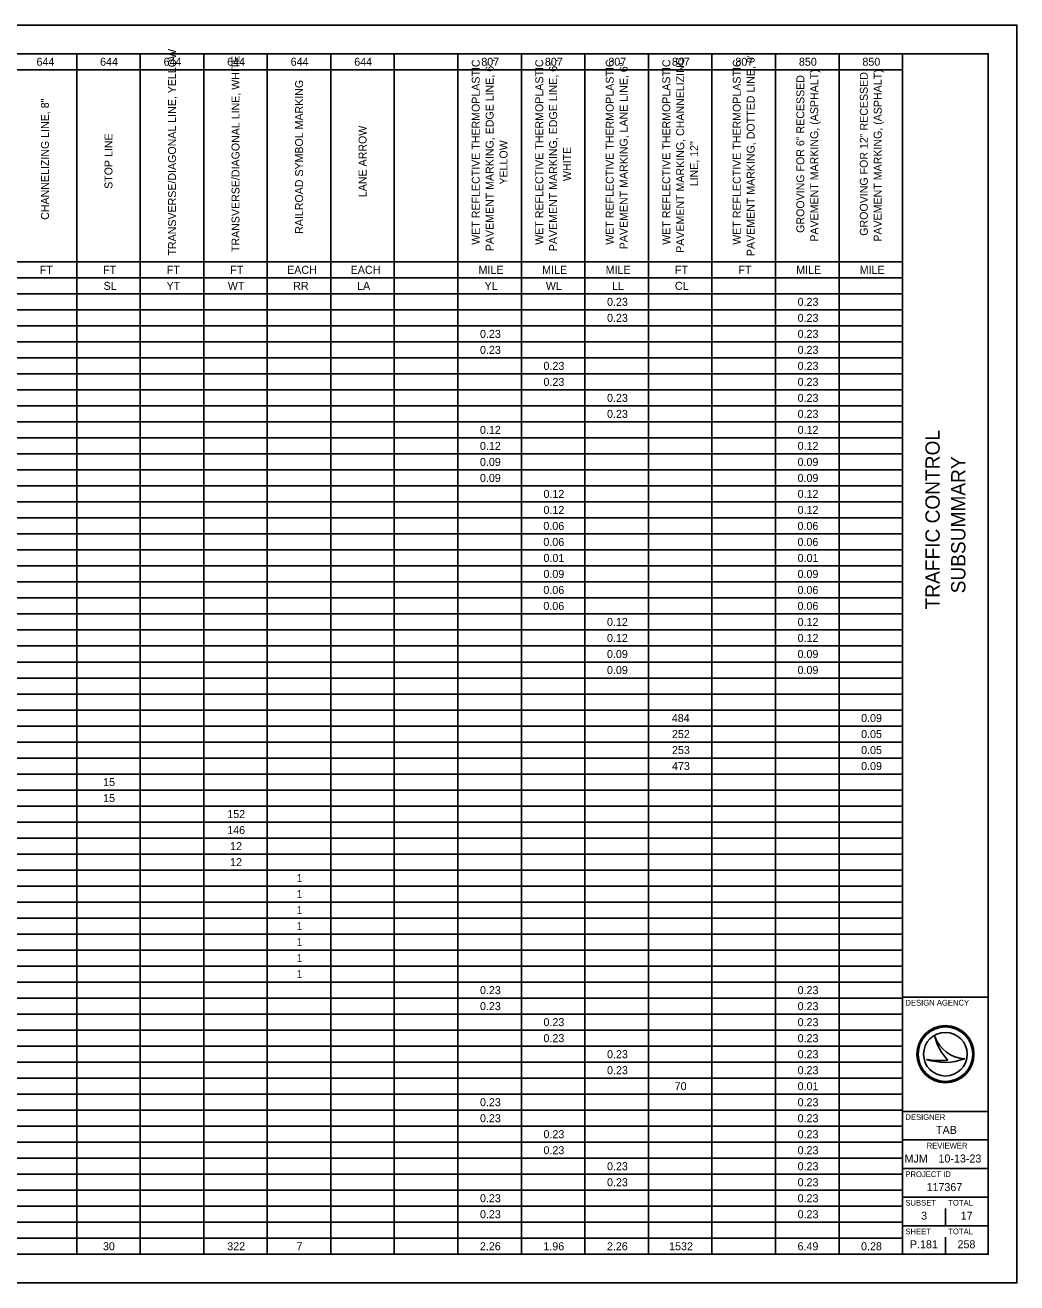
# Model space of a CAD drawing. Extents: x 0 to 34, y 0 to 22.
# Drawn here: x 16.65 to 34, y 0 to 22 of the extents above; entities that cross this region are included whole.
import ezdxf

# ---------------------------------------------------------------- set-up
doc = ezdxf.new("R2010")
doc.units = 0
for name, color, linetype in [('Default', 7, 'Continuous'), ('SH_Border', 7, 'Continuous'), ('SH_Cut_Line', 7, 'Continuous'), ('SH_Data', 7, 'Continuous')]:
    doc.layers.add(name, color=color, linetype=linetype)

msp = doc.modelspace()

# ---------------------------------------------------------------- linework, layer by layer
at = {"layer": 'Default'}
for p, q in [((1.5, 21.5), (32, 21.5)), ((17.551, 21.5), (17.551, 0.5)), ((18.662, 21.5), (18.662, 0.5)), ((19.774, 21.5), (19.774, 0.5)), ((20.885, 21.5), (20.885, 0.5)), ((21.997, 21.5), (21.997, 0.5)), ((23.108, 21.5), (23.108, 0.5)), ((24.22, 21.5), (24.22, 0.5)), ((25.331, 21.5), (25.331, 0.5)), ((26.443, 21.5), (26.443, 0.5)), ((27.554, 21.5), (27.554, 0.5)), ((28.666, 21.5), (28.666, 0.5)), ((29.777, 21.5), (29.777, 0.5)), ((30.889, 21.5), (30.889, 0.5)), ((32, 21.5), (32, 0.5)), ((8.659, 21.22), (32, 21.22)), ((8.659, 17.86), (32, 17.86)), ((1.5, 17.58), (32, 17.58)), ((1.5, 17.3), (32, 17.3)), ((1.5, 17.02), (32, 17.02)), ((1.5, 16.74), (32, 16.74)), ((1.5, 16.46), (32, 16.46)), ((1.5, 16.18), (32, 16.18)), ((1.5, 15.9), (32, 15.9)), ((1.5, 15.62), (32, 15.62)), ((1.5, 15.34), (32, 15.34)), ((1.5, 15.06), (32, 15.06)), ((1.5, 14.78), (32, 14.78)), ((1.5, 14.5), (32, 14.5)), ((1.5, 14.22), (32, 14.22)), ((1.5, 13.94), (32, 13.94)), ((1.5, 13.66), (32, 13.66)), ((1.5, 13.38), (32, 13.38)), ((1.5, 13.1), (32, 13.1)), ((1.5, 12.82), (32, 12.82)), ((1.5, 12.54), (32, 12.54)), ((1.5, 12.26), (32, 12.26)), ((1.5, 11.98), (32, 11.98)), ((1.5, 11.7), (32, 11.7)), ((1.5, 11.42), (32, 11.42)), ((1.5, 11.14), (32, 11.14)), ((1.5, 10.86), (32, 10.86)), ((1.5, 10.58), (32, 10.58)), ((1.5, 10.3), (32, 10.3)), ((1.5, 10.02), (32, 10.02)), ((1.5, 9.74), (32, 9.74)), ((1.5, 9.46), (32, 9.46)), ((1.5, 9.18), (32, 9.18)), ((1.5, 8.9), (32, 8.9)), ((1.5, 8.62), (32, 8.62)), ((1.5, 8.34), (32, 8.34)), ((1.5, 8.06), (32, 8.06)), ((1.5, 7.78), (32, 7.78)), ((1.5, 7.5), (32, 7.5)), ((1.5, 7.22), (32, 7.22)), ((1.5, 6.94), (32, 6.94)), ((1.5, 6.66), (32, 6.66)), ((1.5, 6.38), (32, 6.38)), ((1.5, 6.1), (32, 6.1)), ((1.5, 5.82), (32, 5.82)), ((1.5, 5.54), (32, 5.54)), ((1.5, 5.26), (32, 5.26)), ((1.5, 4.98), (32, 4.98)), ((1.5, 4.7), (32, 4.7)), ((1.5, 4.42), (32, 4.42)), ((1.5, 4.14), (32, 4.14)), ((1.5, 3.86), (32, 3.86)), ((1.5, 3.58), (32, 3.58)), ((1.5, 3.3), (32, 3.3)), ((1.5, 3.02), (32, 3.02)), ((1.5, 2.74), (32, 2.74)), ((1.5, 2.46), (32, 2.46)), ((1.5, 2.18), (32, 2.18)), ((1.5, 1.9), (32, 1.9)), ((1.5, 1.62), (32, 1.62)), ((1.5, 1.34), (32, 1.34)), ((1.5, 1.06), (32, 1.06)), ((1.5, 0.78), (32, 0.78)), ((1.5, 0.5), (32, 0.5))]:
    msp.add_line(p, q, dxfattribs=at)
at = {"layer": 'SH_Border'}
for p, q in [((32, 0.5), (32, 21.5)), ((32, 5), (33.5, 5)), ((32, 3), (33.5, 3)), ((32, 2.5), (33.5, 2.5)), ((32, 2), (33.5, 2)), ((32, 1.5), (33.5, 1.5)), ((32, 1), (33.5, 1))]:
    msp.add_line(p, q, dxfattribs=at)
msp.add_lwpolyline([(1.5, 21.5), (33.5, 21.5), (33.5, 0.5), (1.5, 0.5)], close=True, dxfattribs=at)
at = {"layer": 'SH_Cut_Line'}
msp.add_lwpolyline([(0, 0), (34, 0), (34, 22), (0, 22)], close=True, dxfattribs=at)
at = {"layer": 'SH_Data'}
for p, q in [((32.567, 4.31), (32.567, 4.31)), ((32.75, 4), (32.75, 4)), ((32.417, 3.91), (32.417, 3.91)), ((33.087, 3.919), (33.087, 3.919)), ((32.75, 1), (32.75, 1.3)), ((32.375, 0.675), (32.375, 0.675)), ((32.75, 0.5), (32.75, 0.8))]:
    msp.add_line(p, q, dxfattribs=at)
for radius in [0.5, 0.477, 0.477, 0.382]:
    msp.add_circle((32.75, 4), radius, dxfattribs=at)
for centre, radius, start, end in [((33.116, 4.498), 0.58, 198.9257, 198.9319), ((33.347, 4.47), 0.796, 191.6379, 191.6421), ((33.116, 4.498), 0.58, 198.9319, 267.1657), ((33.347, 4.47), 0.796, 191.6421, 226.0947), ((32.739, 4.87), 1.013, 251.4576, 290.0832), ((32.648, 5.154), 1.266, 259.4964, 259.4995), ((32.739, 4.87), 1.013, 251.4527, 251.4576), ((32.648, 5.154), 1.266, 259.4995, 276.6672)]:
    msp.add_arc(centre, radius, start, end, dxfattribs=at)

# ---------------------------------------------------------------- texts
at = {"layer": 'Default'}
for s, height, p in [('TRANSVERSE/DIAGONAL LINE, YELLOW', 0.13893, (19.288, 17.97)), ('TRANSVERSE/DIAGONAL LINE, WHITE', 0.13893, (20.399, 18.031)), ('WET REFLECTIVE THERMOPLASTIC ', 0.13893, (24.602, 18.159)), ('PAVEMENT MARKING, EDGE LINE, 6", ', 0.13893, (24.845, 18.046)), ('WET REFLECTIVE THERMOPLASTIC ', 0.13893, (25.713, 18.159)), ('PAVEMENT MARKING, EDGE LINE, 6", ', 0.13893, (25.956, 18.046)), ('WET REFLECTIVE THERMOPLASTIC ', 0.13893, (26.946, 18.159)), ('WET REFLECTIVE THERMOPLASTIC ', 0.13893, (27.936, 18.159)), ('PAVEMENT MARKING, CHANNELIZING ', 0.13893, (28.179, 18.017)), ('WET REFLECTIVE THERMOPLASTIC ', 0.13893, (29.169, 18.159)), ('PAVEMENT MARKING, DOTTED LINE, 6"', 0.13893, (29.412, 17.96)), ('PAVEMENT MARKING, LANE LINE, 6"', 0.13893, (27.189, 18.08)), ('PAVEMENT MARKING, (ASPHALT)', 0.13893, (30.524, 18.213)), ('GROOVING FOR 12" RECESSED ', 0.13893, (31.392, 18.316)), ('PAVEMENT MARKING, (ASPHALT)', 0.13893, (31.635, 18.213)), ('RAILROAD SYMBOL MARKING', 0.13893, (21.511, 18.349)), ('GROOVING FOR 6" RECESSED ', 0.13893, (30.281, 18.367)), ('CHANNELIZING LINE, 8"', 0.13893, (17.065, 18.595)), ('LANE ARROW', 0.1389, (22.622, 18.992)), ('STOP LINE', 0.1389, (18.176, 19.136)), ('YELLOW', 0.1389, (25.088, 19.212)), ('WHITE', 0.1389, (26.2, 19.273)), ('LINE, 12"', 0.1389, (28.422, 19.181))]:
    msp.add_text(s, height=height, rotation=90, dxfattribs=at).set_placement(p)
for s, p in [('644', (16.848, 21.29)), ('644', (17.96, 21.29)), ('644', (19.071, 21.29)), ('644', (20.183, 21.29)), ('644', (21.294, 21.29)), ('644', (22.406, 21.29)), ('807', (24.63, 21.29)), ('807', (25.742, 21.29)), ('807', (26.853, 21.29)), ('807', (27.965, 21.29)), ('807', (29.076, 21.29)), ('850', (30.187, 21.29)), ('850', (31.298, 21.29)), ('FT', (16.903, 17.65)), ('FT', (18.014, 17.65)), ('FT', (19.126, 17.65)), ('FT', (20.237, 17.65)), ('EACH', (21.232, 17.65)), ('EACH', (22.344, 17.65)), ('MILE', (24.582, 17.65)), ('MILE', (25.694, 17.65)), ('MILE', (26.805, 17.65)), ('FT', (28.017, 17.65)), ('FT', (29.129, 17.65)), ('MILE', (30.139, 17.65)), ('MILE', (31.251, 17.65)), ('SL', (18.021, 17.37)), ('YT', (19.123, 17.37)), ('WT', (20.195, 17.37)), ('RR', (21.338, 17.37)), ('LA', (22.456, 17.37)), ('YL', (24.687, 17.37)), ('WL', (25.759, 17.37)), ('LL', (26.916, 17.37)), ('CL', (28.017, 17.37)), ('0.23', (26.83, 17.09)), ('0.23', (30.164, 17.09)), ('0.23', (26.83, 16.81)), ('0.23', (30.164, 16.81)), ('0.23', (24.607, 16.53)), ('0.23', (30.164, 16.53)), ('0.23', (24.607, 16.25)), ('0.23', (30.164, 16.25)), ('0.23', (25.718, 15.97)), ('0.23', (30.164, 15.97)), ('0.23', (25.718, 15.69)), ('0.23', (30.164, 15.69)), ('0.23', (26.83, 15.41)), ('0.23', (30.164, 15.41)), ('0.23', (26.83, 15.13)), ('0.23', (30.164, 15.13)), ('0.12', (24.606, 14.85)), ('0.12', (30.164, 14.85)), ('0.12', (24.606, 14.57)), ('0.12', (30.164, 14.57)), ('0.09', (24.606, 14.29)), ('0.09', (30.163, 14.29)), ('0.09', (24.606, 14.01)), ('0.09', (30.163, 14.01)), ('0.12', (25.718, 13.73)), ('0.12', (30.164, 13.73)), ('0.12', (25.718, 13.45)), ('0.12', (30.164, 13.45)), ('0.06', (25.716, 13.17)), ('0.06', (30.162, 13.17)), ('0.06', (25.716, 12.89)), ('0.06', (30.162, 12.89)), ('0.01', (25.718, 12.61)), ('0.01', (30.164, 12.61)), ('0.09', (25.717, 12.33)), ('0.09', (30.163, 12.33)), ('0.06', (25.716, 12.05)), ('0.06', (30.162, 12.05)), ('0.06', (25.716, 11.77)), ('0.06', (30.162, 11.77)), ('0.12', (26.829, 11.49)), ('0.12', (30.164, 11.49)), ('0.12', (26.829, 11.21)), ('0.12', (30.164, 11.21)), ('0.09', (26.829, 10.93)), ('0.09', (30.163, 10.93)), ('0.09', (26.829, 10.65)), ('0.09', (30.163, 10.65)), ('484', (27.963, 9.81)), ('0.09', (31.275, 9.81)), ('252', (27.966, 9.53)), ('0.05', (31.275, 9.53)), ('253', (27.966, 9.25)), ('0.05', (31.275, 9.25)), ('473', (27.966, 8.97)), ('0.09', (31.275, 8.97)), ('15', (18.013, 8.69)), ('15', (18.013, 8.41)), ('152', (20.185, 8.13)), ('146', (20.184, 7.85)), ('12', (20.235, 7.57)), ('12', (20.235, 7.29)), ('1', (21.396, 7.01)), ('1', (21.396, 6.73)), ('1', (21.396, 6.45)), ('1', (21.396, 6.17)), ('1', (21.396, 5.89)), ('1', (21.396, 5.61)), ('1', (21.396, 5.33)), ('0.23', (24.607, 5.05)), ('0.23', (30.164, 5.05)), ('0.23', (24.607, 4.77)), ('0.23', (30.164, 4.77)), ('0.23', (25.718, 4.49)), ('0.23', (30.164, 4.49)), ('0.23', (25.718, 4.21)), ('0.23', (30.164, 4.21)), ('0.23', (26.83, 3.93)), ('0.23', (30.164, 3.93)), ('0.23', (26.83, 3.65)), ('0.23', (30.164, 3.65)), ('70', (28.013, 3.37)), ('0.01', (30.164, 3.37)), ('0.23', (24.607, 3.09)), ('0.23', (30.164, 3.09)), ('0.23', (24.607, 2.81)), ('0.23', (30.164, 2.81)), ('0.23', (25.718, 2.53)), ('0.23', (30.164, 2.53)), ('0.23', (25.718, 2.25)), ('0.23', (30.164, 2.25)), ('0.23', (26.83, 1.97)), ('0.23', (30.164, 1.97)), ('0.23', (26.83, 1.69)), ('0.23', (30.164, 1.69)), ('0.23', (24.607, 1.41)), ('0.23', (30.164, 1.41)), ('0.23', (24.607, 1.13)), ('0.23', (30.164, 1.13)), ('30', (18.01, 0.57)), ('322', (20.185, 0.57)), ('7', (21.396, 0.57)), ('2.26', (24.605, 0.57)), ('1.96', (25.716, 0.57)), ('2.26', (26.828, 0.57)), ('1532', (27.916, 0.57)), ('6.49', (30.163, 0.57)), ('0.28', (31.274, 0.57))]:
    msp.add_text(s, height=0.14, dxfattribs=at).set_placement(p)
at = {"layer": 'SH_Data'}
for s, p in [('TRAFFIC CONTROL', (32.65, 11.78)), ('SUBSUMMARY', (33.1, 12.061))]:
    msp.add_text(s, height=0.25, rotation=90, dxfattribs=at).set_placement(p)
for s, height, p in [('DESIGN AGENCY', 0.1, (32.05, 4.85)), ('DESIGNER', 0.1, (32.05, 2.85)), ('TAB', 0.14, (32.586, 2.605)), ('REVIEWER', 0.1, (32.422, 2.35)), ('MJM', 0.14, (32.035, 2.105)), ('10-13-23', 0.14, (32.629, 2.105)), ('PROJECT ID', 0.1, (32.05, 1.85)), ('117367', 0.14, (32.42, 1.605)), ('SUBSET', 0.1, (32.05, 1.35)), ('TOTAL', 0.1, (32.8, 1.35)), ('3', 0.14, (32.326, 1.105)), ('17', 0.14, (33.018, 1.105)), ('SHEET', 0.1, (32.05, 0.85)), ('TOTAL', 0.1, (32.8, 0.85)), ('P.181', 0.14, (32.129, 0.605)), ('258', 0.14, (32.962, 0.605))]:
    msp.add_text(s, height=height, dxfattribs=at).set_placement(p)

doc.saveas('drawing.dxf')
